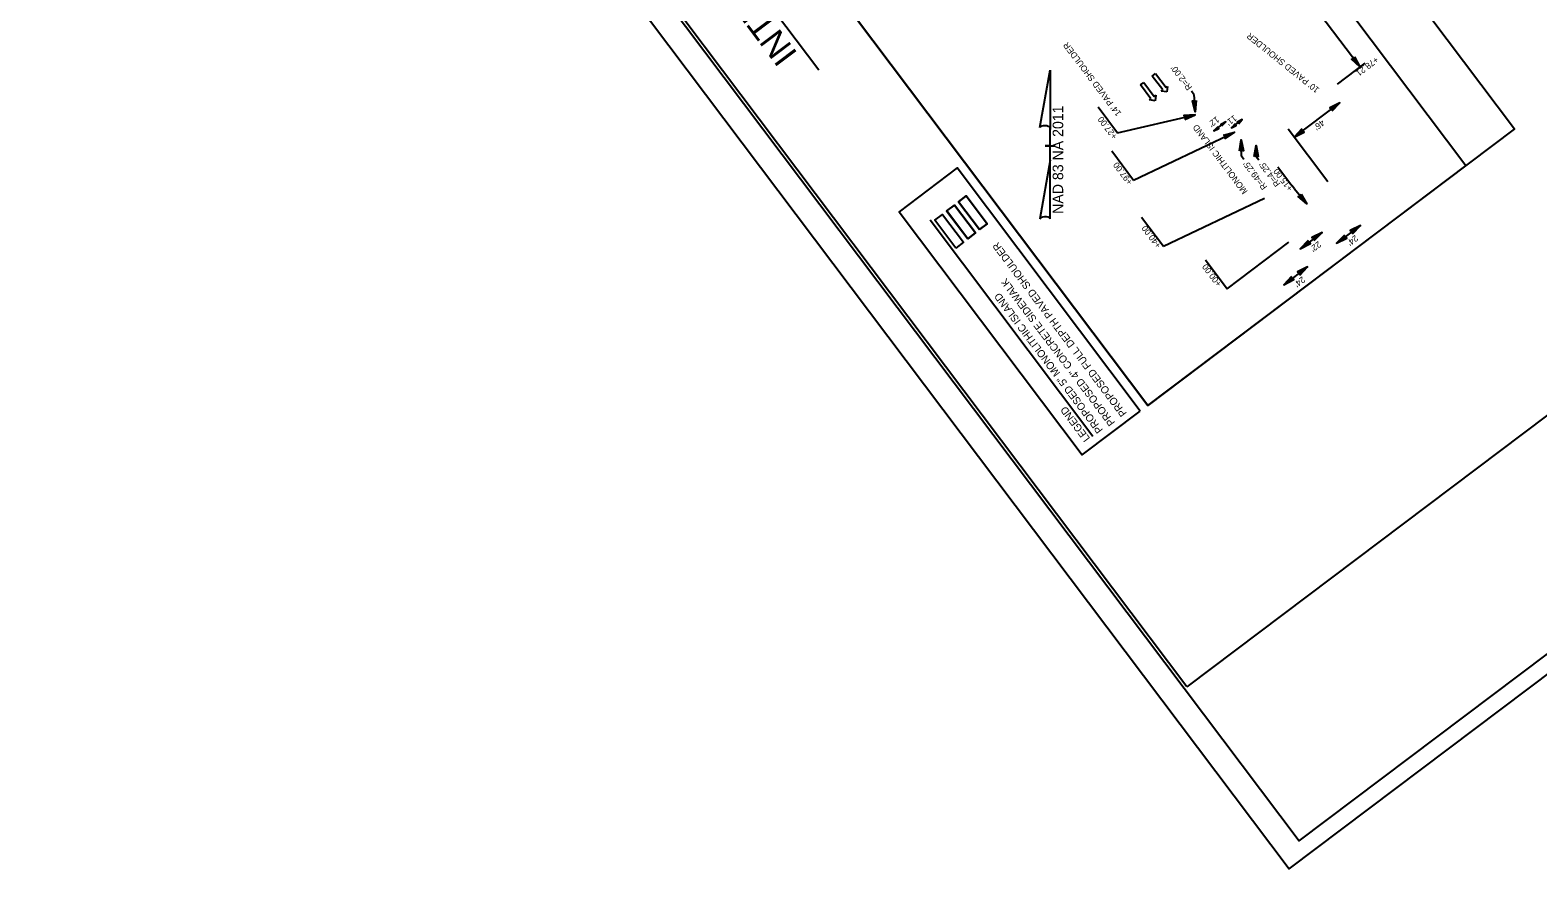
# Model space of a CAD drawing. Extents: x 1262917 to 1264804, y 775326 to 777329.
# Drawn here: x 1262917 to 1264130, y 775326 to 776000 of the extents above; entities that cross this region are included whole.
import ezdxf

# ---------------------------------------------------------------- set-up
doc = ezdxf.new("R2010")
doc.units = 0
for name, color, linetype in [('Old_Level_1', 7, 'Continuous'), ('Prop Dimension', 7, 'Continuous'), ('Prop Dimension Text', 7, 'Continuous'), ('Prop EOT', 7, 'Continuous'), ('Prop Horizontal Alignment Curve and Spiral Data', 7, 'Continuous'), ('Prop Lane Arrow CELL', 7, 'Continuous'), ('Prop Shade Heavy', 7, 'Continuous'), ('Prop Shade Light', 7, 'Continuous'), ('Prop Shade Medium', 7, 'Continuous'), ('Prop Terminator CELL', 7, 'Continuous'), ('Scratch_Level_1', 7, 'Continuous'), ('Sheet Plot Border Inside CELL', 7, 'Continuous'), ('Sheet Plot Border Outside CELL', 7, 'Continuous'), ('Sheet Typical CELL', 7, 'Continuous')]:
    doc.layers.add(name, color=color, linetype=linetype)

msp = doc.modelspace()

# ---------------------------------------------------------------- linework, layer by layer
at = {"layer": 'Old_Level_1'}
for p, q in [((1263728.9, 775922.1), (1263737.1, 775968.4)), ((1263737.1, 775968.4), (1263737.1, 775968.4)), ((1263737.1, 775968.4), (1263737.1, 775968.4)), ((1263737.1, 775968.4), (1263737.1, 775920.6)), ((1263737.1, 775895.8), (1263737.1, 775922)), ((1263737.1, 775920.6), (1263737.1, 775922)), ((1263736.7, 775907.4), (1263733.1, 775907.4)), ((1263733.1, 775907.4), (1263733.1, 775907.4)), ((1263733.2, 775907.4), (1263741.2, 775907.4)), ((1263737.1, 775895.8), (1263728.8, 775848.6)), ((1263737.2, 775848.8), (1263737.1, 775895.8))]:
    msp.add_line(p, q, dxfattribs=at)
for centre, start_param, end_param in [((1263733, 775921.6), 0.216388, 2.908219), ((1263733, 775848.4), 0.201328, 3.141593)]:
    msp.add_ellipse(centre, major_axis=(4.23, -0.03), ratio=0.461098, start_param=start_param, end_param=end_param, dxfattribs=at)
at = {"layer": 'Prop Dimension'}
for p, q in [((1263986.3, 775970.9), (1263878, 776114.7)), ((1263990.3, 775973.9), (1263968, 775957.1)), ((1263771.5, 775673.6), (1263640.6, 775847.5))]:
    msp.add_line(p, q, dxfattribs=at)
at = {"layer": 'Prop Dimension Text'}
for p, q in [((1263852.8, 775948.8), (1263850.8, 775951.5)), ((1263852.9, 775948.7), (1263850.8, 775951.4)), ((1263852.9, 775948.7), (1263850.8, 775951.4)), ((1263852.8, 775948.8), (1263853.8, 775934.7)), ((1263852.9, 775948.7), (1263853.9, 775934.7)), ((1263775.8, 775938.7), (1263791.5, 775917.9)), ((1263791.5, 775917.9), (1263854, 775932.3)), ((1263933.4, 775914.3), (1263970.4, 775942.1)), ((1263868.9, 775919.4), (1263878.5, 775926.6)), ((1263883, 775921.8), (1263891.8, 775928.5)), ((1263960.5, 775878.4), (1263928.6, 775920.7)), ((1263804.3, 775879.9), (1263885.5, 775918.5)), ((1263891.1, 775899.2), (1263891, 775912.4)), ((1263891.1, 775899.2), (1263891, 775912.3)), ((1263786.7, 775903.3), (1263804.3, 775879.9)), ((1263893.1, 775896.5), (1263891.1, 775899.2)), ((1263893.1, 775896.5), (1263891.1, 775899.2)), ((1263903, 775898.5), (1263902.9, 775907.9)), ((1263903, 775898.5), (1263902.9, 775907.8)), ((1263905, 775895.8), (1263903, 775898.5)), ((1263905, 775895.9), (1263903, 775898.5)), ((1263920.5, 775890.4), (1263931.7, 775875.6)), ((1263933.7, 775872.9), (1263931.7, 775875.6)), ((1263933.8, 775872.8), (1263943.8, 775860.7)), ((1263828.5, 775826.6), (1263909.6, 775865.3)), ((1263810.8, 775850), (1263828.5, 775826.6)), ((1263956, 775837.8), (1263938.4, 775824.6)), ((1263986.9, 775843.4), (1263967.7, 775829)), ((1263879.7, 775792.3), (1263929.3, 775830)), ((1263862.1, 775815.7), (1263879.7, 775792.3)), ((1263944.3, 775810.1), (1263925.1, 775795.7))]:
    msp.add_line(p, q, dxfattribs=at)
msp.add_lwpolyline([(1263982.1, 775979), (1263986.3, 775970.9), (1263979.6, 775977.2), (1263981.6, 775977.2)], close=True, dxfattribs=at)
at = {"layer": 'Prop EOT'}
for points in [[(1263670.9, 775832.6), (1263654, 775855), (1263660.2, 775859.7), (1263677, 775837.3)], [(1263680.4, 775840.1), (1263663.5, 775862.5), (1263669.7, 775867.1), (1263686.5, 775844.7)], [(1263661.4, 775825.2), (1263644.5, 775847.6), (1263650.7, 775852.2), (1263667.5, 775829.8)]]:
    msp.add_lwpolyline(points, close=True, dxfattribs=at)
at = {"layer": 'Prop Horizontal Alignment Curve and Spiral Data'}
msp.add_line((1263551.1, 775968.3), (1263316, 776280.5), dxfattribs=at)
at = {"layer": 'Prop Lane Arrow CELL'}
for p, q in [((1263809.9, 775956.4), (1263812.6, 775958.4)), ((1263812.6, 775958.4), (1263821, 775947.2)), ((1263819.4, 775963.5), (1263822, 775965.5)), ((1263827.8, 775952.4), (1263819.4, 775963.5)), ((1263822, 775965.5), (1263830.5, 775954.3)), ((1263818.3, 775945.2), (1263809.9, 775956.4)), ((1263817.1, 775944.3), (1263818.3, 775945.2)), ((1263821, 775947.2), (1263822.2, 775948.1)), ((1263822.2, 775948.1), (1263821.6, 775943.7)), ((1263826.6, 775951.5), (1263827.8, 775952.4)), ((1263831.1, 775950.9), (1263826.6, 775951.5)), ((1263830.5, 775954.3), (1263831.7, 775955.2)), ((1263831.7, 775955.2), (1263831.1, 775950.9)), ((1263821.6, 775943.7), (1263817.1, 775944.3))]:
    msp.add_line(p, q, dxfattribs=at)
at = {"layer": 'Prop Shade Heavy'}
for p, q in [((1263661.4, 775825.2), (1263644.5, 775847.6)), ((1263650.7, 775852.2), (1263667.5, 775829.8)), ((1263667.5, 775829.8), (1263661.4, 775825.2)), ((1263661.4, 775825.2), (1263661.4, 775825.2))]:
    msp.add_line(p, q, dxfattribs=at)
msp.add_ellipse((1263650.7, 775852.2), major_axis=(-0.000000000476, -0.000000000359), ratio=0.894427, start_param=3.141593, end_param=3.521844, dxfattribs=at)
at = {"layer": 'Prop Shade Light'}
for p, q in [((1263669.7, 775867.1), (1263663.4, 775862.4)), ((1263663.4, 775862.4), (1263680.4, 775840.1)), ((1263680.4, 775840.1), (1263686.5, 775844.7))]:
    msp.add_line(p, q, dxfattribs=at)
msp.add_lwpolyline([(1263686.5, 775844.7), (1263669.7, 775867.1)], dxfattribs=at)
msp.add_ellipse((1263663.4, 775862.4), major_axis=(-0.018, -0.0081), ratio=0.299083, start_param=5.584494, end_param=6.511789, dxfattribs=at)
at = {"layer": 'Prop Shade Medium'}
for p, q in [((1263660.2, 775859.7), (1263653.9, 775855)), ((1263653.9, 775855), (1263670.9, 775832.6)), ((1263670.9, 775832.6), (1263677, 775837.3))]:
    msp.add_line(p, q, dxfattribs=at)
msp.add_lwpolyline([(1263677, 775837.3), (1263660.2, 775859.7)], dxfattribs=at)
msp.add_ellipse((1263653.9, 775855), major_axis=(-0.018, -0.0081), ratio=0.299083, start_param=5.584494, end_param=6.511789, dxfattribs=at)
at = {"layer": 'Prop Terminator CELL'}
for points in [[(1263845.5, 775928.7), (1263854, 775932.3), (1263844.8, 775931.8), (1263846.3, 775930.5)], [(1263854.8, 775943.8), (1263853.9, 775934.7), (1263851.6, 775943.6), (1263853.3, 775942.6)], [(1263964.1, 775935.5), (1263970.4, 775942.1), (1263962.2, 775938), (1263964, 775937.4)], [(1263872, 775922.7), (1263868.9, 775919.4), (1263872.9, 775921.4), (1263872, 775921.7)], [(1263875.4, 775923.4), (1263878.5, 775926.6), (1263874.5, 775924.6), (1263875.4, 775924.3)], [(1263886.1, 775925.1), (1263883, 775921.8), (1263887, 775923.9), (1263886.1, 775924.2)], [(1263888.7, 775925.2), (1263891.8, 775928.5), (1263887.8, 775926.4), (1263888.7, 775926.1)], [(1263939.7, 775921), (1263933.4, 775914.3), (1263941.6, 775918.5), (1263939.7, 775919.1)], [(1263876.7, 775916), (1263885.5, 775918.5), (1263878, 775913.2), (1263878.4, 775915.1)], [(1263889.5, 775903.3), (1263891, 775912.3), (1263892.7, 775903.3), (1263891.1, 775904.4)], [(1263901.4, 775898.8), (1263902.9, 775907.8), (1263904.6, 775898.8), (1263903, 775899.9)], [(1263939.2, 775868.6), (1263943.8, 775860.7), (1263936.8, 775866.6), (1263938.7, 775866.7)], [(1263949.7, 775831.2), (1263956, 775837.8), (1263947.8, 775833.7), (1263949.7, 775833.1)], [(1263973.9, 775835.6), (1263967.7, 775829), (1263975.9, 775833.1), (1263974, 775833.7)], [(1263980.6, 775836.7), (1263986.9, 775843.4), (1263978.7, 775839.2), (1263980.5, 775838.6)], [(1263944.7, 775831.2), (1263938.4, 775824.6), (1263946.6, 775828.8), (1263944.7, 775829.3)], [(1263931.4, 775802.4), (1263925.1, 775795.7), (1263933.3, 775799.9), (1263931.4, 775800.5)], [(1263938, 775803.5), (1263944.3, 775810.1), (1263936.1, 775806), (1263938, 775805.4)]]:
    msp.add_lwpolyline(points, close=True, dxfattribs=at)
at = {"layer": 'Scratch_Level_1'}
msp.add_lwpolyline([(1263815.7, 775698.6), (1263313.4, 776365.4), (1263569.5, 776558.3), (1264071.7, 775891.5)], close=True, dxfattribs=at)
at = {"layer": 'Sheet Plot Border Inside CELL'}
msp.add_lwpolyline([(1264780.2, 775982.9), (1263777.9, 777313.6), (1262935.2, 776678.9), (1263937.5, 775348.2)], close=True, dxfattribs=at)
at = {"layer": 'Sheet Plot Border Outside CELL'}
msp.add_lwpolyline([(1262916.5, 776670.5), (1263929.4, 775325.7), (1264804, 775984.5), (1263791.2, 777329.3)], close=True, dxfattribs=at)
at = {"layer": 'Sheet Typical CELL'}
for p, q in [((1263847.2, 775472.3), (1262944.7, 776670.4)), ((1264685.9, 776104), (1263847.2, 775472.3))]:
    msp.add_line(p, q, dxfattribs=at)
for points in [[(1263313.4, 776365.4), (1263815.7, 775698.6), (1264110.7, 775920.9), (1263608.5, 776587.6)], [(1263809.6, 775694), (1263662.3, 775889.6), (1263615.6, 775854.4), (1263762.9, 775658.9)]]:
    msp.add_lwpolyline(points, close=True, dxfattribs=at)

# ---------------------------------------------------------------- texts
at = {"layer": 'Old_Level_1'}
msp.add_text('NAD 83 NA 2011', height=8.5, rotation=90, dxfattribs=at).set_placement((1263747.7, 775852.7))
at = {"layer": 'Prop Dimension'}
for s, rotation, p in [("10' PAVED SHOULDER", 141.2327, (1263954.2, 775953.4)), ("14' PAVED SHOULDER", 126.9874, (1263794.7, 775933.6)), ("R=2.00'", 126.9874, (1263851.7, 775954.5)), ('+27.00', 126.9874, (1263791.5, 775915.1)), ('MONOLITHIC ISLAND', 126.9874, (1263896.4, 775870.9)), ('+97.00', 126.9874, (1263803.9, 775878.4)), ("R=49.25'", 126.9874, (1263912.1, 775874.4)), ("R=4.25'", 126.9874, (1263922.7, 775876.9)), ('+15.00', 126.9874, (1263932.8, 775873.3)), ('+40.00', 126.9874, (1263826.8, 775827.5)), ('+00.00', 126.9874, (1263875.5, 775796.5))]:
    msp.add_text(s, height=5, rotation=rotation, dxfattribs=at).set_placement(p)
at = {"layer": 'Prop Dimension Text'}
for s, height, rotation, p in [('+78.21', 5, 216.9874, (1263999.1, 775979.5)), ("12'", 5, 216.9874, (1263871, 775931.4)), ("11'", 5, 216.9874, (1263885.1, 775932.5)), ("46'", 5, 216.9874, (1263955.8, 775928.8)), ("24'", 5, 216.9874, (1263982.6, 775835.9)), ('PROPOSED FULL DEPTH PAVED SHOULDER ', 6, 126.9877, (1263799.2, 775692.3)), ("22'", 5, 216.9874, (1263952.9, 775831)), ('PROPOSED 4" CONCRETE SIDEWALK', 6, 126.9877, (1263789.7, 775684.8)), ("24'", 5, 216.9874, (1263940, 775802.6)), ('PROPOSED 5" MONOLITHIC ISLAND', 6, 126.9877, (1263780, 775678.9)), ('LEGEND', 6, 126.9877, (1263769.6, 775672.1))]:
    msp.add_text(s, height=height, rotation=rotation, dxfattribs=at).set_placement(p)
at = {"layer": 'Prop Horizontal Alignment Curve and Spiral Data'}
msp.add_text('INTERSECTION DETAILS', height=20, rotation=126.9874, dxfattribs=at).set_placement((1263534.5, 775981.6))

doc.saveas('drawing.dxf')
